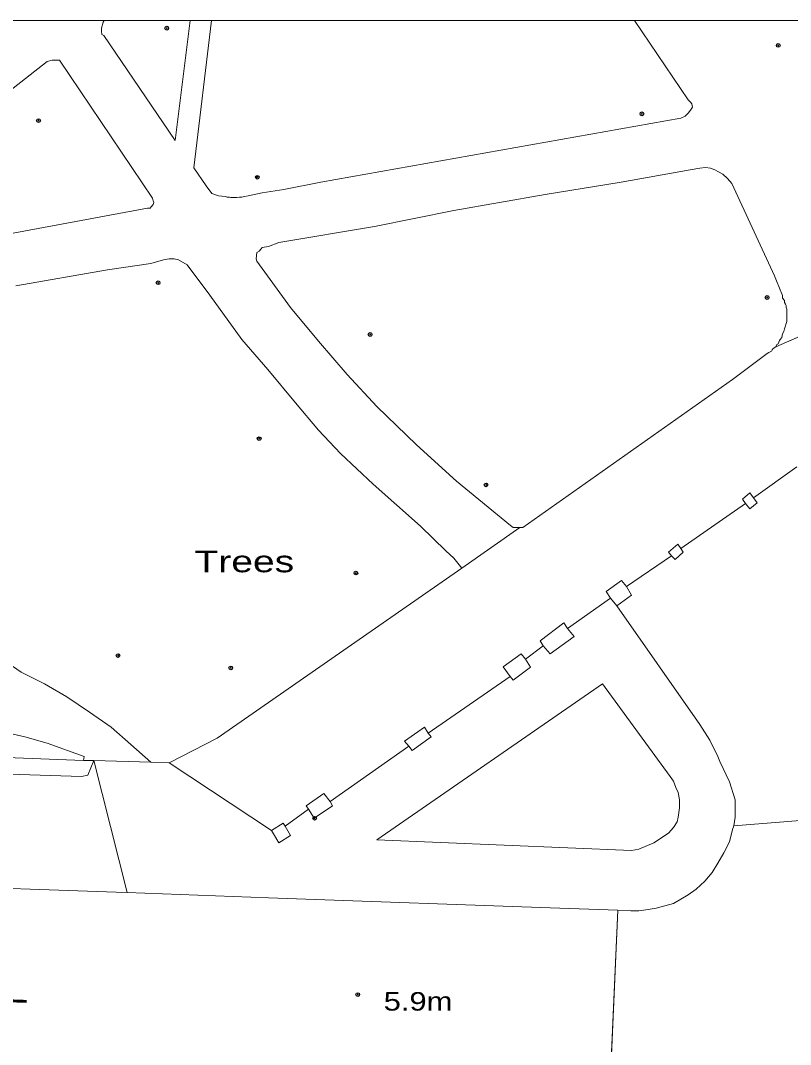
# Model space of a CAD drawing. Extents: x 528790 to 529292, y 179350 to 179856.
# Drawn here: x 529045.4 to 529107.9, y 179772.9 to 179856 of the extents above; entities that cross this region are included whole.
import ezdxf

# ---------------------------------------------------------------- set-up
doc = ezdxf.new("R2010")
doc.units = 0
doc.header["$LTSCALE"] = 0.6
doc.header["$PDMODE"] = 32
doc.header["$PDSIZE"] = 0.3
for name, color, linetype, lineweight in [('1', 7, 'Continuous', 13), ('2', 7, 'Continuous', 13), ('7', 7, 'Continuous', 13)]:
    doc.layers.add(name, color=color, linetype=linetype, lineweight=lineweight)
for name, color, linetype in [('3', 7, 'Continuous'), ('4', 7, 'Continuous'), ('5', 7, 'Continuous')]:
    doc.layers.add(name, color=color, linetype=linetype)

msp = doc.modelspace()

# ---------------------------------------------------------------- linework, layer by layer
at = {"layer": '1'}
for points in [[(529112.683, 179856.024), (529095.242, 179856.024), (529099.6, 179849.6), (529099.8, 179849.4), (529099.9, 179849.25), (529099.95, 179849), (529099.8, 179848.75), (529099.6, 179848.5), (529099.35, 179848.25), (529099, 179848.1), (529069.8, 179842.9), (529066.8, 179842.3), (529065.05, 179842.05), (529063.9, 179841.8), (529063.6, 179841.75), (529063.4, 179841.7), (529063.2, 179841.7), (529063, 179841.65), (529062.5, 179841.65), (529062.4, 179841.7), (529062.2, 179841.7), (529062.05, 179841.75), (529061.5, 179841.8), (529060.95, 179842), (529060.5, 179842.6), (529059.497, 179844.074), (529060.923, 179856.024), (529059.208, 179856.024), (529057.999, 179846.275), (529052.2, 179854.8), (529052.05, 179854.9), (529052, 179855.15), (529052, 179855.4), (529052.15, 179855.9), (529052.233, 179856.024), (529045.379, 179856.024)], [(529045.05, 179834.5), (529052.5, 179835.8), (529056, 179836.3), (529057.05, 179836.6), (529057.5, 179836.7), (529057.9, 179836.7), (529058.25, 179836.6), (529058.95, 179836.2), (529060.8, 179833.75), (529063.4, 179830.15), (529065.5, 179827.7), (529067.75, 179825), (529069.6, 179822.8), (529071.4, 179820.9), (529074.05, 179818.4), (529077.9, 179815), (529079.95, 179813), (529080.6, 179812.4), (529081.25, 179811.6), (529085.95, 179814.9), (529085.4, 179814.9), (529085.2, 179815.05), (529080.8, 179818.65), (529077.55, 179821.6), (529074.35, 179824.7), (529071.95, 179827.3), (529069.6, 179830), (529067.35, 179832.75), (529064.6, 179836.5), (529064.55, 179836.7), (529064.6, 179837.2), (529064.8, 179837.3), (529064.95, 179837.5), (529065.05, 179837.6), (529065.55, 179837.7), (529066.4, 179838), (529074.15, 179839.3), (529080.6, 179840.6), (529088, 179841.9), (529094.15, 179842.9), (529099.75, 179843.9), (529100.55, 179844.05), (529101, 179844.1), (529101.4, 179844.05), (529101.75, 179843.9), (529102.05, 179843.75), (529102.4, 179843.55), (529102.8, 179843.2), (529103.15, 179842.8), (529106.6, 179835.3), (529106.75, 179834.9), (529107.25, 179833.7), (529107.25, 179833.5), (529107.4, 179833.3), (529107.4, 179833.15), (529107.5, 179833), (529107.55, 179832.9), (529107.55, 179832.75), (529107.6, 179832.6), (529107.6, 179831.6), (529107.4, 179831), (529107.35, 179830.8), (529107.25, 179830.6), (529107.2, 179830.3), (529107.05, 179830.15), (529107, 179830.05), (529106.9, 179829.8), (529106.8, 179829.75), (529106.7, 179829.55), (529131.609, 179840.415)], [(529131.609, 179840.415), (529106.7, 179829.55), (529106.5, 179829.4), (529106.4, 179829.3), (529106.35, 179829.2), (529106.15, 179829.1), (529106, 179829), (529103.2, 179826.9), (529086.2, 179814.9), (529085.95, 179814.9), (529081.25, 179811.6), (529061.4, 179797.8), (529057.5, 179795.8), (529065.8, 179790.3), (529066.75, 179790.9), (529066.9, 179790.65), (529068.8, 179792.05), (529068.6, 179792.3), (529070.05, 179793.3), (529070.55, 179792.65), (529076.95, 179797.15), (529076.6, 179797.55), (529078.2, 179798.7), (529078.5, 179798.2), (529085.15, 179802.8), (529084.6, 179803.6), (529086.05, 179804.65), (529086.4, 179804.2), (529087.85, 179805.3), (529087.6, 179805.7), (529089.5, 179807.15), (529089.8, 179806.7), (529093.3, 179809.15), (529092.95, 179809.7), (529094.2, 179810.6), (529094.6, 179810.1), (529098.25, 179812.6), (529098, 179812.9), (529098.75, 179813.55), (529099, 179813.2), (529104.25, 179816.85), (529104, 179817.2), (529104.6, 179817.7), (529104.9, 179817.3), (529108.4, 179819.8)], [(529044.8, 179803.65), (529045.5, 179803.15), (529047.4, 179802.2), (529049.2, 179801.15), (529051.05, 179799.9), (529052.8, 179798.7), (529054.4, 179797.3), (529056, 179795.85), (529057.5, 179795.8), (529061.4, 179797.8), (529081.25, 179811.6), (529080.6, 179812.4), (529079.95, 179813), (529077.9, 179815), (529074.05, 179818.4), (529071.4, 179820.9), (529069.6, 179822.8), (529067.75, 179825), (529065.5, 179827.7), (529063.4, 179830.15), (529060.8, 179833.75), (529058.95, 179836.2), (529058.25, 179836.6), (529057.9, 179836.7), (529057.5, 179836.7), (529057.05, 179836.6), (529056, 179836.3), (529052.5, 179835.8), (529045.05, 179834.5)], [(529108.4, 179819.8), (529104.9, 179817.3), (529105.2, 179816.9), (529104.6, 179816.4), (529104.25, 179816.85), (529099, 179813.2), (529099.2, 179812.9), (529098.55, 179812.3), (529098.25, 179812.6), (529094.6, 179810.1), (529095, 179809.4), (529093.8, 179808.55), (529100.55, 179798.9), (529101.35, 179797.65), (529102, 179796.3), (529102.179, 179795.914), (529102.95, 179794.25), (529103.4, 179792.8), (529103.4, 179791.4), (529103.3, 179790.7), (529128.9, 179792.746)], [(529045.5, 179803.15), (529044.8, 179803.65)], [(529044.25, 179798.25), (529045.8, 179797.9), (529047.6, 179797.4), (529050.6, 179796.3), (529050.55, 179796), (529051.4, 179795.98), (529056, 179795.85), (529054.4, 179797.3), (529052.8, 179798.7), (529051.05, 179799.9), (529049.2, 179801.15), (529047.4, 179802.2), (529045.5, 179803.15)], [(529035.95, 179796.55), (529050.55, 179796), (529050.6, 179796.3), (529047.6, 179797.4), (529045.8, 179797.9), (529044.25, 179798.25)], [(529000, 179796.3), (529050.4, 179794.7), (529050.9, 179794.8), (529051.4, 179795.98), (529050.55, 179796), (529035.95, 179796.55)], [(529128.9, 179792.746), (529103.3, 179790.7), (529103.2, 179790.4), (529102.95, 179789.4), (529102.5, 179788.5), (529102, 179787.65), (529101.55, 179786.9), (529100.95, 179786.2), (529100.25, 179785.55), (529099.6, 179785.1), (529098.4, 179784.4), (529097, 179784), (529096.35, 179783.9), (529095.6, 179783.8), (529094.95, 179783.8), (529093.884, 179783.837), (529093.19, 179767.75)], [(529093.19, 179767.75), (529093.884, 179783.837), (529088.41, 179784.03), (529067.065, 179784.796), (529065.55, 179784.85), (529054.104, 179785.267), (529053.2, 179785.3), (529037.68, 179785.84)]]:
    msp.add_lwpolyline(points, dxfattribs=at)
for points in [[(529059.208, 179856.024), (529052.233, 179856.024), (529052.15, 179855.9), (529052, 179855.4), (529052, 179855.15), (529052.05, 179854.9), (529052.2, 179854.8), (529057.999, 179846.275)], [(529095.242, 179856.024), (529060.923, 179856.024), (529059.497, 179844.074), (529060.5, 179842.6), (529060.95, 179842), (529061.5, 179841.8), (529062.05, 179841.75), (529062.2, 179841.7), (529062.4, 179841.7), (529062.5, 179841.65), (529063, 179841.65), (529063.2, 179841.7), (529063.4, 179841.7), (529063.6, 179841.75), (529063.9, 179841.8), (529065.05, 179842.05), (529066.8, 179842.3), (529069.8, 179842.9), (529099, 179848.1), (529099.35, 179848.25), (529099.6, 179848.5), (529099.8, 179848.75), (529099.95, 179849), (529099.9, 179849.25), (529099.8, 179849.4), (529099.6, 179849.6)], [(529056.25, 179841.25), (529056.2, 179841.4), (529056.15, 179841.6), (529048.6, 179852.8), (529048, 179852.8), (529047.6, 179852.7), (529030.9, 179839.6), (529029.95, 179838.8), (529029.6, 179838.5), (529029.2, 179837.7), (529029, 179837.25), (529029, 179836.8), (529029.2, 179836.55), (529029.35, 179836.3), (529029.55, 179836.2), (529029.8, 179836.05), (529030.15, 179836), (529030.4, 179836.05), (529030.7, 179836.15), (529055.75, 179840.8), (529055.95, 179840.8), (529056.05, 179840.9), (529056.2, 179841.1)], [(529056.15, 179841.6), (529056.2, 179841.4), (529056.25, 179841.25), (529056.2, 179841.1), (529056.05, 179840.9), (529055.95, 179840.8), (529055.75, 179840.8), (529030.7, 179836.15), (529030.4, 179836.05), (529030.15, 179836), (529029.8, 179836.05), (529029.55, 179836.2), (529029.35, 179836.3), (529029.2, 179836.55), (529029, 179836.8), (529029, 179837.25), (529029.2, 179837.7), (529029.6, 179838.5), (529029.95, 179838.8), (529030.9, 179839.6), (529047.6, 179852.7), (529048, 179852.8), (529048.6, 179852.8)], [(529085.95, 179814.9), (529086.2, 179814.9), (529103.2, 179826.9), (529106, 179829), (529106.15, 179829.1), (529106.35, 179829.2), (529106.4, 179829.3), (529106.5, 179829.4), (529106.7, 179829.55), (529106.8, 179829.75), (529106.9, 179829.8), (529107, 179830.05), (529107.05, 179830.15), (529107.2, 179830.3), (529107.25, 179830.6), (529107.35, 179830.8), (529107.4, 179831), (529107.6, 179831.6), (529107.6, 179832.6), (529107.55, 179832.75), (529107.55, 179832.9), (529107.5, 179833), (529107.4, 179833.15), (529107.4, 179833.3), (529107.25, 179833.5), (529107.25, 179833.7), (529106.75, 179834.9), (529106.6, 179835.3), (529103.15, 179842.8), (529102.8, 179843.2), (529102.4, 179843.55), (529102.05, 179843.75), (529101.75, 179843.9), (529101.4, 179844.05), (529101, 179844.1), (529100.55, 179844.05), (529099.75, 179843.9), (529094.15, 179842.9), (529088, 179841.9), (529080.6, 179840.6), (529074.15, 179839.3), (529066.4, 179838), (529065.55, 179837.7), (529065.05, 179837.6), (529064.95, 179837.5), (529064.8, 179837.3), (529064.6, 179837.2), (529064.55, 179836.7), (529064.6, 179836.5), (529067.35, 179832.75), (529069.6, 179830), (529071.95, 179827.3), (529074.35, 179824.7), (529077.55, 179821.6), (529080.8, 179818.65), (529085.2, 179815.05), (529085.4, 179814.9)], [(529104.9, 179817.3), (529104.6, 179817.7), (529104, 179817.2), (529104.25, 179816.85), (529104.6, 179816.4), (529105.2, 179816.9)], [(529099, 179813.2), (529098.75, 179813.55), (529098, 179812.9), (529098.25, 179812.6), (529098.55, 179812.3), (529099.2, 179812.9)], [(529094.6, 179810.1), (529094.2, 179810.6), (529092.95, 179809.7), (529093.3, 179809.15), (529093.8, 179808.55), (529095, 179809.4)], [(529093.8, 179808.55), (529093.3, 179809.15), (529089.8, 179806.7), (529090.35, 179806.05), (529088.4, 179804.65), (529087.85, 179805.3), (529086.4, 179804.2), (529086.8, 179803.55), (529085.4, 179802.5), (529085.15, 179802.8), (529078.5, 179798.2), (529078.75, 179797.9), (529077.2, 179796.8), (529076.95, 179797.15), (529070.55, 179792.65), (529070.75, 179792.3), (529069.25, 179791.3), (529068.8, 179792.05), (529066.9, 179790.65), (529067.35, 179789.9), (529066.4, 179789.3), (529065.95, 179790.05), (529065.8, 179790.3), (529057.5, 179795.8), (529056, 179795.85), (529051.4, 179795.98), (529054.104, 179785.267), (529065.55, 179784.85), (529067.065, 179784.796), (529088.41, 179784.03), (529093.884, 179783.837), (529094.95, 179783.8), (529095.6, 179783.8), (529096.35, 179783.9), (529097, 179784), (529098.4, 179784.4), (529099.6, 179785.1), (529100.25, 179785.55), (529100.95, 179786.2), (529101.55, 179786.9), (529102, 179787.65), (529102.5, 179788.5), (529102.95, 179789.4), (529103.2, 179790.4), (529103.3, 179790.7), (529103.4, 179791.4), (529103.4, 179792.8), (529102.95, 179794.25), (529102.179, 179795.914), (529102, 179796.3), (529101.35, 179797.65), (529100.55, 179798.9)], [(529089.8, 179806.7), (529089.5, 179807.15), (529087.6, 179805.7), (529087.85, 179805.3), (529088.4, 179804.65), (529090.35, 179806.05)], [(529086.4, 179804.2), (529086.05, 179804.65), (529084.6, 179803.6), (529085.15, 179802.8), (529085.4, 179802.5), (529086.8, 179803.55)], [(528790.22, 179803.571), (528790.22, 179792.969), (528808.03, 179792.34), (528995.96, 179785.29), (529000, 179785.35), (529037.68, 179785.84), (529053.2, 179785.3), (529054.104, 179785.267), (529051.4, 179795.98), (529050.9, 179794.8), (529050.4, 179794.7), (529000, 179796.3), (528993.8, 179796.4), (528981.6, 179796.8), (528965.2, 179797.3), (528930, 179798.6), (528909.95, 179799.3), (528893.75, 179799.8), (528872.4, 179800.6), (528854.3, 179801.2), (528838.3, 179801.8), (528825.75, 179802.2), (528810.7, 179802.65), (528793.8, 179803.3)], [(529074.35, 179789.55), (529095, 179788.7), (529095.6, 179788.8), (529096.8, 179789.3), (529098, 179790.1), (529098.4, 179790.55), (529098.7, 179791), (529098.8, 179791.4), (529098.9, 179792.15), (529098.9, 179792.8), (529098.8, 179793.4), (529098.6, 179793.8), (529098.4, 179794.3), (529098.15, 179794.7), (529092.65, 179802.2)], [(529092.65, 179802.2), (529098.15, 179794.7), (529098.4, 179794.3), (529098.6, 179793.8), (529098.8, 179793.4), (529098.9, 179792.8), (529098.9, 179792.15), (529098.8, 179791.4), (529098.7, 179791), (529098.4, 179790.55), (529098, 179790.1), (529096.8, 179789.3), (529095.6, 179788.8), (529095, 179788.7), (529074.35, 179789.55)], [(529078.5, 179798.2), (529078.2, 179798.7), (529076.6, 179797.55), (529076.95, 179797.15), (529077.2, 179796.8), (529078.75, 179797.9)], [(529070.55, 179792.65), (529070.05, 179793.3), (529068.6, 179792.3), (529068.8, 179792.05), (529069.25, 179791.3), (529070.75, 179792.3)], [(529066.9, 179790.65), (529066.75, 179790.9), (529065.8, 179790.3), (529065.95, 179790.05), (529066.4, 179789.3), (529067.35, 179789.9)]]:
    msp.add_lwpolyline(points, close=True, dxfattribs=at)
at = {"layer": '2'}
for p, q in [((529059.208, 179856.024), (529057.999, 179846.275)), ((529131.609, 179840.415), (529106.7, 179829.55)), ((529104.9, 179817.3), (529108.4, 179819.8)), ((529099, 179813.2), (529104.25, 179816.85)), ((529081.25, 179811.6), (529085.95, 179814.9)), ((529094.6, 179810.1), (529098.25, 179812.6)), ((529089.8, 179806.7), (529093.3, 179809.15)), ((529093.8, 179808.55), (529093.3, 179809.15)), ((529086.4, 179804.2), (529087.85, 179805.3)), ((529078.5, 179798.2), (529085.15, 179802.8)), ((529070.55, 179792.65), (529076.95, 179797.15)), ((529050.55, 179796), (529051.4, 179795.98)), ((529054.104, 179785.267), (529051.4, 179795.98)), ((529051.4, 179795.98), (529056, 179795.85)), ((529056, 179795.85), (529057.5, 179795.8)), ((529065.8, 179790.3), (529057.5, 179795.8)), ((529066.9, 179790.65), (529068.8, 179792.05)), ((529093.19, 179767.75), (529093.884, 179783.837))]:
    msp.add_line(p, q, dxfattribs=at)
for points in [[(529057.999, 179846.275), (529052.2, 179854.8), (529052.05, 179854.9), (529052, 179855.15), (529052, 179855.4), (529052.15, 179855.9), (529052.233, 179856.024)], [(529060.95, 179842), (529060.5, 179842.6), (529059.497, 179844.074), (529060.923, 179856.024)], [(529095.242, 179856.024), (529099.6, 179849.6), (529099.8, 179849.4), (529099.9, 179849.25), (529099.95, 179849), (529099.8, 179848.75), (529099.6, 179848.5), (529099.35, 179848.25), (529099, 179848.1), (529069.8, 179842.9)], [(529106.7, 179829.55), (529106.8, 179829.75), (529106.9, 179829.8), (529107, 179830.05), (529107.05, 179830.15), (529107.2, 179830.3), (529107.25, 179830.6), (529107.35, 179830.8), (529107.4, 179831), (529107.6, 179831.6), (529107.6, 179832.6), (529107.55, 179832.75), (529107.55, 179832.9), (529107.5, 179833), (529107.4, 179833.15), (529107.4, 179833.3), (529107.25, 179833.5), (529107.25, 179833.7), (529106.75, 179834.9), (529106.6, 179835.3), (529103.15, 179842.8), (529102.8, 179843.2), (529102.4, 179843.55), (529102.05, 179843.75), (529101.75, 179843.9), (529101.4, 179844.05), (529101, 179844.1), (529100.55, 179844.05), (529099.75, 179843.9), (529094.15, 179842.9), (529088, 179841.9), (529080.6, 179840.6), (529074.15, 179839.3), (529066.4, 179838), (529065.55, 179837.7), (529065.05, 179837.6), (529064.95, 179837.5), (529064.8, 179837.3), (529064.6, 179837.2), (529064.55, 179836.7), (529064.6, 179836.5), (529067.35, 179832.75), (529069.6, 179830), (529071.95, 179827.3), (529074.35, 179824.7), (529077.55, 179821.6), (529080.8, 179818.65), (529085.2, 179815.05), (529085.4, 179814.9), (529085.95, 179814.9)], [(529069.8, 179842.9), (529066.8, 179842.3), (529065.05, 179842.05), (529063.9, 179841.8), (529063.6, 179841.75), (529063.4, 179841.7), (529063.2, 179841.7), (529063, 179841.65), (529062.5, 179841.65), (529062.4, 179841.7), (529062.2, 179841.7), (529062.05, 179841.75), (529061.5, 179841.8), (529060.95, 179842)], [(529045.05, 179834.5), (529052.5, 179835.8), (529056, 179836.3), (529057.05, 179836.6), (529057.5, 179836.7), (529057.9, 179836.7), (529058.25, 179836.6), (529058.95, 179836.2), (529060.8, 179833.75), (529063.4, 179830.15), (529065.5, 179827.7), (529067.75, 179825), (529069.6, 179822.8), (529071.4, 179820.9), (529074.05, 179818.4), (529077.9, 179815), (529079.95, 179813), (529080.6, 179812.4), (529081.25, 179811.6)], [(529085.95, 179814.9), (529086.2, 179814.9), (529103.2, 179826.9), (529106, 179829), (529106.15, 179829.1), (529106.35, 179829.2), (529106.4, 179829.3), (529106.5, 179829.4), (529106.7, 179829.55)], [(529104.25, 179816.85), (529104, 179817.2), (529104.6, 179817.7), (529104.9, 179817.3)], [(529104.9, 179817.3), (529105.2, 179816.9), (529104.6, 179816.4), (529104.25, 179816.85)], [(529099, 179813.2), (529098.75, 179813.55), (529098, 179812.9), (529098.25, 179812.6)], [(529099, 179813.2), (529099.2, 179812.9), (529098.55, 179812.3), (529098.25, 179812.6)], [(529057.5, 179795.8), (529061.4, 179797.8), (529081.25, 179811.6)], [(529094.6, 179810.1), (529094.2, 179810.6), (529092.95, 179809.7), (529093.3, 179809.15)], [(529094.6, 179810.1), (529095, 179809.4), (529093.8, 179808.55)], [(529093.8, 179808.55), (529100.55, 179798.9), (529101.35, 179797.65), (529102, 179796.3), (529102.179, 179795.914)], [(529089.8, 179806.7), (529089.5, 179807.15), (529087.6, 179805.7), (529087.85, 179805.3)], [(529089.8, 179806.7), (529090.35, 179806.05), (529088.4, 179804.65), (529087.85, 179805.3)], [(528790.22, 179805.058), (528798.35, 179804.8), (528817.8, 179804.1), (528838.8, 179803.3), (528856.7, 179802.7), (528876.75, 179801.9), (528898.2, 179801.2), (528936.4, 179799.8), (528958.4, 179799.05), (528979.4, 179798.3), (528995.8, 179797.8), (529000, 179797.7), (529035.95, 179796.55), (529050.55, 179796)], [(529085.15, 179802.8), (529084.6, 179803.6), (529086.05, 179804.65), (529086.4, 179804.2)], [(528790.22, 179803.571), (528793.8, 179803.3), (528810.7, 179802.65), (528825.75, 179802.2), (528838.3, 179801.8), (528854.3, 179801.2), (528872.4, 179800.6), (528893.75, 179799.8), (528909.95, 179799.3), (528930, 179798.6), (528965.2, 179797.3), (528981.6, 179796.8), (528993.8, 179796.4), (529000, 179796.3), (529050.4, 179794.7), (529050.9, 179794.8), (529051.4, 179795.98)], [(529045.5, 179803.15), (529044.8, 179803.65)], [(529086.4, 179804.2), (529086.8, 179803.55), (529085.4, 179802.5), (529085.15, 179802.8)], [(529056, 179795.85), (529054.4, 179797.3), (529052.8, 179798.7), (529051.05, 179799.9), (529049.2, 179801.15), (529047.4, 179802.2), (529045.5, 179803.15)], [(529078.5, 179798.2), (529078.2, 179798.7), (529076.6, 179797.55), (529076.95, 179797.15)], [(529050.55, 179796), (529050.6, 179796.3), (529047.6, 179797.4), (529045.8, 179797.9), (529044.25, 179798.25)], [(529078.5, 179798.2), (529078.75, 179797.9), (529077.2, 179796.8), (529076.95, 179797.15)], [(529102.179, 179795.914), (529102.95, 179794.25), (529103.4, 179792.8), (529103.4, 179791.4), (529103.3, 179790.7)], [(528790.22, 179792.969), (528808.03, 179792.34), (528995.96, 179785.29), (529000, 179785.35), (529037.68, 179785.84), (529053.2, 179785.3), (529054.104, 179785.267)], [(529070.55, 179792.65), (529070.05, 179793.3), (529068.6, 179792.3), (529068.8, 179792.05)], [(529103.3, 179790.7), (529128.9, 179792.746), (529129.489, 179792.793)], [(529070.55, 179792.65), (529070.75, 179792.3), (529069.25, 179791.3), (529068.8, 179792.05)], [(529065.8, 179790.3), (529066.75, 179790.9), (529066.9, 179790.65)], [(529066.9, 179790.65), (529067.35, 179789.9), (529066.4, 179789.3), (529065.95, 179790.05), (529065.8, 179790.3)], [(529093.884, 179783.837), (529094.95, 179783.8), (529095.6, 179783.8), (529096.35, 179783.9), (529097, 179784), (529098.4, 179784.4), (529099.6, 179785.1), (529100.25, 179785.55), (529100.95, 179786.2), (529101.55, 179786.9), (529102, 179787.65), (529102.5, 179788.5), (529102.95, 179789.4), (529103.2, 179790.4), (529103.3, 179790.7)], [(529054.104, 179785.267), (529065.55, 179784.85), (529067.065, 179784.796)], [(529067.065, 179784.796), (529088.41, 179784.03), (529093.884, 179783.837)]]:
    msp.add_lwpolyline(points, dxfattribs=at)
for points in [[(529056.25, 179841.25), (529056.2, 179841.1), (529056.05, 179840.9), (529055.95, 179840.8), (529055.75, 179840.8), (529030.7, 179836.15), (529030.4, 179836.05), (529030.15, 179836), (529029.8, 179836.05), (529029.55, 179836.2), (529029.35, 179836.3), (529029.2, 179836.55), (529029, 179836.8), (529029, 179837.25), (529029.2, 179837.7), (529029.6, 179838.5), (529029.95, 179838.8), (529030.9, 179839.6), (529047.6, 179852.7), (529048, 179852.8), (529048.6, 179852.8), (529056.15, 179841.6), (529056.2, 179841.4)], [(529074.35, 179789.55), (529092.65, 179802.2), (529098.15, 179794.7), (529098.4, 179794.3), (529098.6, 179793.8), (529098.8, 179793.4), (529098.9, 179792.8), (529098.9, 179792.15), (529098.8, 179791.4), (529098.7, 179791), (529098.4, 179790.55), (529098, 179790.1), (529096.8, 179789.3), (529095.6, 179788.8), (529095, 179788.7)]]:
    msp.add_lwpolyline(points, close=True, dxfattribs=at)
at = {"layer": '3'}
for p in [(529057.3, 179855.4), (529106.9, 179854), (529095.85, 179848.45), (529046.9, 179847.9), (529064.65, 179843.3), (529056.6, 179834.75), (529106, 179833.55), (529073.8, 179830.55), (529064.8, 179822.1), (529083.2, 179818.35), (529072.65, 179811.2), (529053.35, 179804.5), (529062.5, 179803.5), (529072.8, 179777)]:
    msp.add_point(p, dxfattribs=at)
at = {"layer": '4'}
msp.add_point((529069.3, 179791.3), dxfattribs=at)
at = {"layer": '7'}
msp.add_lwpolyline([(528790.22, 179356.024), (529290.22, 179356.024), (529290.22, 179856.024), (528790.22, 179856.024)], close=True, dxfattribs=at)

# ---------------------------------------------------------------- texts
at = {"layer": '5'}
for s, height, width, p in [('Trees', 1.75, 1.35, (529059.56, 179811.26)), ('5.9m', 1.5, 1.25, (529074.9, 179775.7))]:
    msp.add_text(s, height=height, dxfattribs=dict(at, width=width)).set_placement(p)
at = {"layer": '5', "width": 1.25}
msp.add_text('CONSTITUTION HILL', height=2.125, rotation=358, dxfattribs=at).set_placement((529010.95, 179777.55))

doc.saveas('drawing.dxf')
